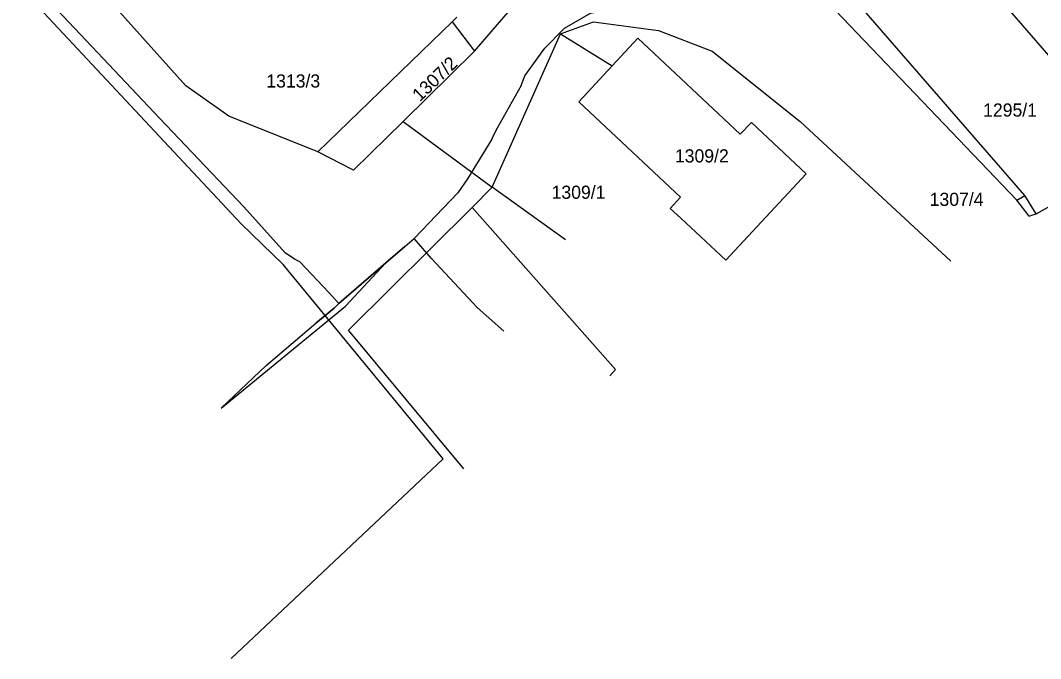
# Model space of a CAD drawing. Extents: x -601580 to 4, y -1204314 to 4.
# Drawn here: x -599977.2 to -599880.4, y -1203586.7 to -1203526.1 of the extents above; entities that cross this region are included whole.
import ezdxf

# ---------------------------------------------------------------- set-up
doc = ezdxf.new("R2010")
doc.units = 0
for name, color, linetype in [('00-KN-HRANICE PARCEL', 7, 'Continuous'), ('00-KN-PARC. CISLA', 7, 'Continuous'), ('00-SITE KOM. KABEL', 7, 'Continuous')]:
    doc.layers.add(name, color=color, linetype=linetype)

msp = doc.modelspace()

# ---------------------------------------------------------------- linework, layer by layer
at = {"layer": '00-KN-HRANICE PARCEL'}
for p, q in [((-599881.87, -1203542.73), (-599904.74, -1203516.35)), ((-599887.07, -1203520.75), (-599871.22, -1203539.18)), ((-599948.98, -1203538.56), (-599936.24, -1203526.24)), ((-599935.77, -1203525.79), (-599936.24, -1203526.24)), ((-599936.24, -1203526.24), (-599934.12, -1203529.01)), ((-599925.95, -1203527.38), (-599921.02, -1203530.4)), ((-599934.12, -1203529.01), (-599940.88, -1203535.68)), ((-599940.88, -1203535.68), (-599932.42, -1203541.93)), ((-599903.18, -1203535.68), (-599888.89, -1203548.96)), ((-599932.42, -1203541.93), (-599934.34, -1203543.84)), ((-599925.47, -1203546.93), (-599932.42, -1203541.93)), ((-599882.63, -1203543.17), (-599881.87, -1203542.73)), ((-599880.78, -1203544.45), (-599881.87, -1203542.73)), ((-599880.78, -1203544.45), (-599876.4, -1203542.03)), ((-599881.44, -1203544.68), (-599882.63, -1203543.17)), ((-599881.44, -1203544.68), (-599881.28, -1203544.62)), ((-599881.28, -1203544.62), (-599880.78, -1203544.45))]:
    msp.add_line(p, q, dxfattribs=at)
for points in [[(-599948.98, -1203538.56), (-599957.44, -1203535.19), (-599961.51, -1203532.31), (-599977.69, -1203514.25), (-599980.58, -1203507), (-599975.75, -1203503.07)], [(-599957.21, -1203586.66), (-599937.08, -1203567.71), (-599952.28, -1203549.27), (-599956.27, -1203545.4), (-599985.98, -1203513.66), (-599987.68, -1203513.29), (-600018.7, -1203537.48), (-600027.97, -1203545.34), (-600031.55, -1203548.65)], [(-599882.63, -1203543.17), (-599903.32, -1203521.48), (-599906.49, -1203518.05)], [(-599934.12, -1203529.01), (-599931.32, -1203525.78), (-599929.55, -1203523.74)], [(-599925.95, -1203527.38), (-599922.82, -1203526.24), (-599916.65, -1203527.07), (-599911.54, -1203529.01), (-599903.18, -1203535.68)], [(-599932.42, -1203541.93), (-599928.38, -1203532.86), (-599925.95, -1203527.38)], [(-599921.02, -1203530.4), (-599918.6, -1203527.79), (-599908.89, -1203536.88), (-599907.82, -1203535.8), (-599902.61, -1203540.65), (-599910.23, -1203548.86), (-599914.53, -1203544.87)], [(-599914.53, -1203544.87), (-599915.52, -1203543.95), (-599914.56, -1203542.87), (-599924.2, -1203533.84), (-599921.02, -1203530.4)], [(-599940.88, -1203535.68), (-599945.58, -1203540.31), (-599948.98, -1203538.56)], [(-599935.11, -1203568.64), (-599946.06, -1203555.5), (-599934.34, -1203543.84)], [(-599934.34, -1203543.84), (-599920.71, -1203559.24), (-599921.27, -1203559.82)]]:
    msp.add_lwpolyline(points, dxfattribs=at)
at = {"layer": '00-SITE KOM. KABEL'}
for points in [[(-599946.97, -1203552.96), (-599947.92, -1203551.91), (-599950.7, -1203549), (-599951.21, -1203548.75), (-599952.07, -1203548.17), (-599956.02, -1203543.8), (-599963.99, -1203535.42), (-599980.23, -1203518.24), (-599985.53, -1203512.82), (-599988.04, -1203510.93), (-599989.41, -1203509.72), (-599994.23, -1203503.41), (-599994.29, -1203503.06)], [(-599946.97, -1203552.96), (-599947.92, -1203551.91), (-599950.7, -1203549), (-599951.21, -1203548.75), (-599952.07, -1203548.17), (-599956.02, -1203543.8), (-599963.99, -1203535.42), (-599980.23, -1203518.24), (-599985.53, -1203512.82), (-599988.04, -1203510.93), (-599989.41, -1203509.72), (-599994.23, -1203503.41), (-599994.29, -1203503.06)], [(-599929.69, -1203532.27), (-599929.34, -1203531.36), (-599927.43, -1203528.72), (-599925.56, -1203526.85), (-599923.09, -1203525.41), (-599920.05, -1203524.82), (-599916.15, -1203524.47), (-599913.41, -1203524.67), (-599909.73, -1203525.2), (-599902.46, -1203524.81), (-599900.71, -1203523.86), (-599900.08, -1203523.39), (-599899.52, -1203522.27), (-599899.23, -1203519.5)], [(-599929.69, -1203532.27), (-599931.94, -1203536.34), (-599932.386, -1203537.178)], [(-599932.449, -1203537.372), (-599934.76, -1203541.13), (-599935.69, -1203542.47), (-599939.82, -1203546.78)], [(-599932.386, -1203537.178), (-599932.449, -1203537.372)], [(-599935.69, -1203542.47), (-599939.82, -1203546.78)], [(-599952.07, -1203548.17), (-599956.02, -1203543.8)], [(-599940.72, -1203547.56), (-599942.52, -1203549.09), (-599946.97, -1203552.96)], [(-599942.52, -1203549.09), (-599940.72, -1203547.56), (-599939.82, -1203546.78)], [(-599931.31, -1203555.6), (-599933.84, -1203553.35), (-599938.2, -1203548.7), (-599939.82, -1203546.78)], [(-599950.7, -1203549), (-599951.21, -1203548.75), (-599952.07, -1203548.17)], [(-599958.15, -1203562.9), (-599946.35, -1203553.22), (-599942.52, -1203549.09)], [(-599946.97, -1203552.96), (-599942.52, -1203549.09)], [(-599958.15, -1203562.9), (-599953.89, -1203558.84), (-599949.16, -1203554.82), (-599947.42, -1203553.41), (-599946.97, -1203552.96)], [(-599947.42, -1203553.41), (-599949.16, -1203554.82)]]:
    msp.add_lwpolyline(points, dxfattribs=at)

# ---------------------------------------------------------------- texts
at = {"layer": '00-KN-PARC. CISLA'}
msp.add_text('1307/2', height=1.25, rotation=44, dxfattribs=at).set_placement((-599939.286, -1203533.867))
for s, p in [('1313/3', (-599953.868, -1203532.47)), ('1295/1', (-599885.815, -1203535.23)), ('1309/2', (-599915.078, -1203539.58)), ('1309/1', (-599926.785, -1203543.03)), ('1307/4', (-599890.888, -1203543.7))]:
    msp.add_text(s, height=1.25, dxfattribs=at).set_placement(p)

doc.saveas('drawing.dxf')
